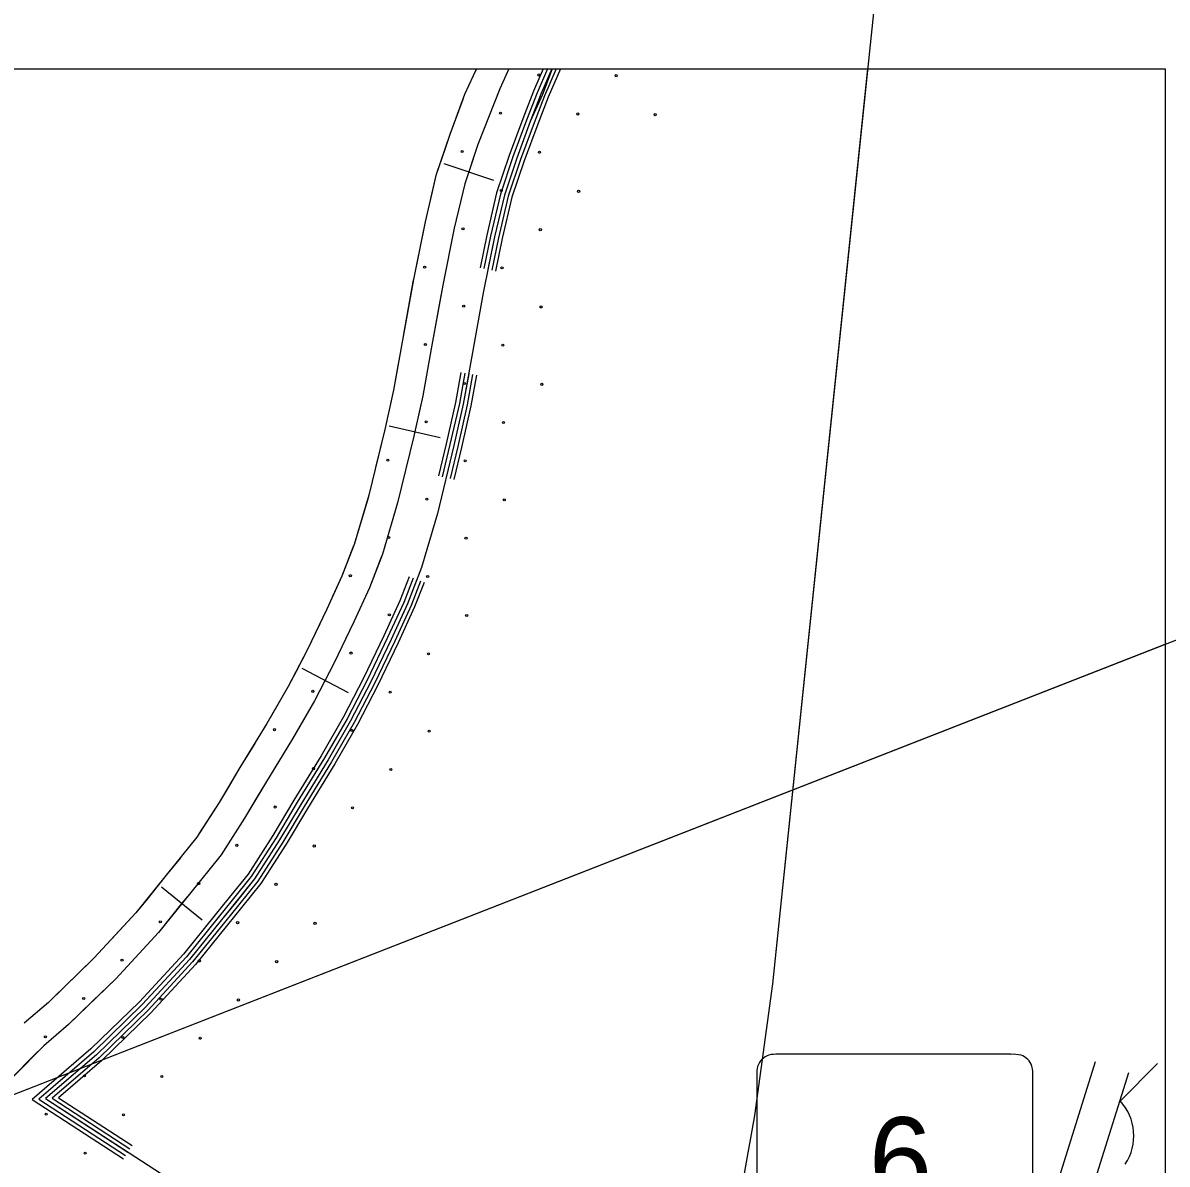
# Model space of a CAD drawing. Extents: x 1577619 to 1828281, y 483481 to 598136.
# Drawn here: x 1689939 to 1695627, y 521065 to 526740 of the extents above; entities that cross this region are included whole.
import ezdxf

# ---------------------------------------------------------------- set-up
doc = ezdxf.new("R2010")
doc.units = 0
for name, color, linetype in [('DESIGN - CENTERLINE - Proposed Text', 7, 'Continuous'), ('DESIGN - CONTOURS - Intermediate with optional Text', 7, 'Continuous'), ('DESIGN - EROSION CONTROL - Devices', 7, 'Continuous'), ('DESIGN - ROW - Slope Lines', 7, 'Continuous'), ('DESIGN - SHEET - Linework', 7, 'Continuous'), ('SURVEY - CENTERLINE - Preliminary', 7, 'Continuous'), ('SURVEY - CENTERLINE - Preliminary Text', 7, 'Continuous'), ('SURVEY - DRAINAGE - Bridge Deck with Text', 7, 'Continuous'), ('SURVEY - DRAINAGE - Natural Features', 7, 'Continuous'), ('SURVEY - VEGETATION - Features with Text', 7, 'Continuous')]:
    doc.layers.add(name, color=color, linetype=linetype)

msp = doc.modelspace()

# ---------------------------------------------------------------- linework, layer by layer
at = {"layer": 'DESIGN - CENTERLINE - Proposed Text'}
for q in [(1697294.5, 524306.5), (1695618, 523650.8)]:
    msp.add_line((1681456.9, 518112.3), q, dxfattribs=at)
at = {"layer": 'DESIGN - CONTOURS - Intermediate with optional Text'}
for p, q in [((1692031.8, 526040.7), (1692278.2, 525957.8)), ((1691760.3, 524736.3), (1692013.8, 524678.7)), ((1691325.6, 523530.6), (1691556.5, 523410.9)), ((1690628.1, 522444), (1690830.4, 522280.7))]:
    msp.add_line(p, q, dxfattribs=at)
for points in [[(1692354.3, 526510.7), (1692309.5, 526411.2), (1692200.9, 526135.9), (1692135, 525939.7), (1692083.3, 525719.5), (1692025.7, 525436.5), (1691968.8, 525118.4), (1691927.3, 524884.8), (1691881.9, 524684.9), (1691801.8, 524353.1), (1691725.7, 524097.5), (1691661.4, 523930.4), (1691583.6, 523761.7), (1691484.6, 523554.8), (1691388.1, 523368.6), (1691279.5, 523180.4), (1691144.6, 522960.1), (1691040.4, 522785), (1690924.1, 522603.4), (1690766.4, 522408.3), (1690612.2, 522217.3), (1690399.9, 521987.3), (1690166, 521759.8), (1690042.2, 521653.7)], [(1692354.3, 526510.7), (1692309.5, 526411.2), (1692200.9, 526135.9), (1692155, 525999.3)], [(1692155, 525999.3), (1692135, 525939.7), (1692083.3, 525719.5), (1692025.7, 525436.5), (1692011.2, 525355.6)], [(1692011.2, 525355.6), (1691968.8, 525118.4), (1691927.3, 524884.8), (1691887, 524707.5)], [(1691887, 524707.5), (1691881.9, 524684.9), (1691801.8, 524353.1), (1691725.7, 524097.5), (1691715.3, 524070.6)], [(1691715.3, 524070.6), (1691661.4, 523930.4), (1691583.6, 523761.7), (1691484.6, 523554.8), (1691441.1, 523470.8)], [(1691441.1, 523470.8), (1691388.1, 523368.6), (1691279.5, 523180.4), (1691144.6, 522960.1), (1691109.1, 522900.5)], [(1691109.1, 522900.5), (1691040.4, 522785), (1690924.1, 522603.4), (1690766.4, 522408.3), (1690729.3, 522362.4)], [(1690729.3, 522362.4), (1690612.2, 522217.3), (1690399.9, 521987.3), (1690284.8, 521875.3)], [(1690284.8, 521875.3), (1690166, 521759.8), (1690042.2, 521653.7)], [(1687255, 518732.8), (1688399.1, 519989.9), (1689031.6, 520639.6), (1689595.9, 521203.2), (1690042.2, 521653.7)], [(1689987.2, 521598.1), (1690042.2, 521653.7)], [(1689522.2, 521129.7), (1689595.9, 521203.2), (1689987.2, 521598.1)]]:
    msp.add_lwpolyline(points, dxfattribs=at)
at = {"layer": 'DESIGN - EROSION CONTROL - Devices'}
for centre in [(1692503.5, 526481.1), (1692888, 526477.4), (1692313.1, 526290.7), (1692697.6, 526287), (1693082.2, 526283.3), (1692122.7, 526100.3), (1692507.2, 526096.6), (1692316.8, 525906.2), (1692701.4, 525902.4), (1692126.4, 525715.8), (1692510.9, 525712), (1691936, 525525.4), (1692320.5, 525521.6), (1692130.1, 525331.2), (1692514.7, 525327.5), (1691939.7, 525140.8), (1692324.3, 525137.1), (1692133.9, 524946.7), (1692518.4, 524942.9), (1691943.5, 524756.2), (1692328, 524752.5), (1691753, 524565.8), (1692137.6, 524562.1), (1691947.2, 524371.7), (1692331.7, 524368), (1691756.8, 524181.3), (1692141.3, 524177.6), (1691566.4, 523990.9), (1691950.9, 523987.1), (1691760.5, 523796.7), (1692145.1, 523793), (1691570.1, 523606.3), (1691954.7, 523602.6), (1691379.7, 523415.9), (1691764.2, 523412.2), (1691189.3, 523225.5), (1691573.8, 523221.8), (1691958.4, 523218), (1691383.4, 523031.4), (1691768, 523027.6), (1691193, 522840.9), (1691577.6, 522837.2), (1691002.6, 522650.5), (1691387.2, 522646.8), (1690812.2, 522460.1), (1691196.7, 522456.4), (1690621.8, 522269.7), (1691006.3, 522266), (1691390.9, 522262.3), (1690431.4, 522079.3), (1690815.9, 522075.6), (1691200.5, 522071.8), (1690241, 521888.9), (1690625.5, 521885.2), (1691010.1, 521881.4), (1690050.6, 521698.5), (1690435.1, 521694.8), (1690819.7, 521691), (1690244.7, 521504.3), (1690629.3, 521500.6), (1690054.3, 521313.9), (1690438.8, 521310.2), (1690248.4, 521119.8)]:
    msp.add_circle(centre, 5.28, dxfattribs=at)
at = {"layer": 'DESIGN - ROW - Slope Lines'}
for p, q in [((1694849.3, 521611.1), (1693692.4, 521611.1)), ((1693587.2, 521509.8), (1693587.2, 520678.1)), ((1694960.1, 520679.5), (1694960.1, 521499.4))]:
    msp.add_line(p, q, dxfattribs=at)
for centre, radius, start, end in [((1693676.1, 521522.2), 89.8, 108.3712, 161.4495), ((1693683.1, 521451), 160.4, 86.6485, 102.7003), ((1694858.4, 521413), 198.2, 77.6972, 92.6427), ((1694870.6, 521521.6), 90.3, 20.2626, 70.5275), ((1693800, 521511), 212.8, 169.2361, 180.3208), ((1694706.5, 521503.7), 253.6, 359.0167, 11.1675)]:
    msp.add_arc(centre, radius, start, end, dxfattribs=at)
at = {"layer": 'DESIGN - SHEET - Linework'}
msp.add_lwpolyline([(1669171.5, 526510.7), (1695618, 526510.7), (1695618, 508119.9), (1669171.5, 508119.9)], close=True, dxfattribs=at)
at = {"layer": 'SURVEY - CENTERLINE - Preliminary'}
for points in [[(1699664.1, 538980.8), (1699319.1, 538409.9), (1698972.3, 537842.5), (1695481.3, 532468.9), (1695357.3, 532233.8), (1695216.5, 531898.8), (1695066.9, 531469.7), (1694585.2, 529330), (1694371.3, 528155.8), (1694207.2, 527174.4), (1693664.5, 521961.3), (1693575.1, 521307.5), (1693482.8, 520785.8), (1693198.2, 519751.4), (1691958.7, 516195.2)], [(1699664.1, 538980.8), (1699319.1, 538409.9), (1698972.3, 537842.5), (1695481.3, 532468.9), (1695357.3, 532233.8), (1695216.5, 531898.8), (1695066.9, 531469.7), (1694585.2, 529330), (1694371.3, 528155.8), (1694207.2, 527174.4), (1693664.5, 521961.3), (1693575.1, 521307.5), (1693482.8, 520785.8), (1693198.2, 519751.4), (1691958.7, 516195.2)], [(1694138.1, 526510.7), (1693664.5, 521961.3), (1693575.1, 521307.5), (1693482.8, 520785.8), (1693198.2, 519751.4), (1691958.7, 516195.2)], [(1694138.1, 526510.7), (1693664.5, 521961.3), (1693575.1, 521307.5), (1693482.8, 520785.8), (1693198.2, 519751.4), (1691958.7, 516195.2)]]:
    msp.add_lwpolyline(points, dxfattribs=at)
at = {"layer": 'SURVEY - CENTERLINE - Preliminary Text'}
for points in [[(1695269.4, 521574.5), (1694992.2, 520687.8), (1694894.5, 520468.7), (1694713.7, 520191.2), (1694544.4, 519986.7)], [(1695434.9, 521519.3), (1695155.6, 520626), (1695048.2, 520385), (1694854.4, 520087.6), (1694679.2, 519876)]]:
    msp.add_lwpolyline(points, dxfattribs=at)
at = {"layer": 'SURVEY - DRAINAGE - Bridge Deck with Text'}
msp.add_line((1695579.9, 521565.4), (1695393, 521378.6), dxfattribs=at)
msp.add_arc((1695207.3, 521206.3), 254.2, 326.2853, 43.0079, dxfattribs=at)
at = {"layer": 'SURVEY - DRAINAGE - Natural Features'}
for points in [[(1692569.4, 526510.7), (1692522.4, 526384.6), (1692461.3, 526249.5), (1692393.8, 526066.7), (1692332.2, 525883.5), (1692283.4, 525675.6), (1692226.9, 525398), (1692170.5, 525082.4), (1692128.1, 524844.1), (1692081.3, 524638.2), (1691999.7, 524299.8), (1691919.7, 524031.4), (1691850.2, 523850.7), (1691769, 523674.5), (1691668, 523463.4), (1691567.8, 523270.2), (1691455.6, 523075.6), (1691320, 522854.2), (1691214.7, 522677.4), (1691090.5, 522483.4), (1690925.7, 522279.6), (1690767.4, 522083.4), (1690546.7, 521844.3), (1690304.2, 521608.4), (1690050.6, 521391.1), (1692863.1, 519564.5)], [(1692568.3, 526510.7), (1692513.3, 526385.3), (1692461.3, 526249.5), (1692393.8, 526066.7), (1692332.2, 525883.5), (1692283.4, 525675.6), (1692226.9, 525398), (1692170.5, 525082.4), (1692128.1, 524844.1), (1692081.3, 524638.2), (1691999.7, 524299.8), (1691919.7, 524031.4), (1691850.2, 523850.7), (1691769, 523674.5), (1691668, 523463.4), (1691567.8, 523270.2), (1691455.6, 523075.6), (1691320, 522854.2), (1691214.7, 522677.4), (1691090.5, 522483.4), (1690925.7, 522279.6), (1690767.4, 522083.4), (1690546.7, 521844.3), (1690304.2, 521608.4), (1690050.6, 521391.1), (1692863.1, 519564.5)], [(1692524.6, 526510.7), (1692476.3, 526400.5), (1692423.9, 526263.6), (1692356.1, 526080), (1692293.7, 525894.5), (1692244.3, 525684.2), (1692211.3, 525521.8)], [(1692546.5, 526510.7), (1692494.8, 526392.9), (1692442.6, 526256.5), (1692374.9, 526073.3), (1692313, 525889), (1692263.8, 525679.9), (1692230.9, 525517.8)], [(1692568.3, 526510.7), (1692513.3, 526385.3), (1692461.3, 526249.5), (1692393.8, 526066.7), (1692332.2, 525883.5), (1692283.4, 525675.6), (1692250.5, 525513.8)], [(1692590.1, 526510.7), (1692531.8, 526377.7), (1692480.1, 526242.5), (1692412.6, 526060), (1692351.5, 525878), (1692302.9, 525671.4), (1692270.1, 525509.9)], [(1692610.9, 526510.7), (1692549.4, 526370.5), (1692497.9, 526235.8), (1692430.6, 526053.7), (1692369.8, 525872.8), (1692321.5, 525667.3), (1692288.7, 525506.1)], [(1692115.5, 525001.6), (1692088.9, 524852.1), (1692042.4, 524647.3), (1692004, 524488.1)], [(1692135.2, 524998.1), (1692108.5, 524848.1), (1692061.9, 524642.7), (1692023.4, 524483.4)], [(1692154.9, 524994.6), (1692128.1, 524844.1), (1692081.3, 524638.2), (1692042.9, 524478.7)], [(1692174.6, 524991.1), (1692147.7, 524840.2), (1692100.8, 524633.6), (1692062.3, 524474.1)], [(1692193.3, 524987.7), (1692166.3, 524836.4), (1692119.3, 524629.3), (1692080.8, 524469.6)], [(1691859.4, 523986.1), (1691813.4, 523866.2), (1691732.8, 523691.6), (1691632.1, 523481.2), (1691532.7, 523289.4), (1691421.2, 523096.1), (1691285.7, 522874.9), (1691180.6, 522698.4), (1691058, 522506.8), (1690963.7, 522390.2)], [(1691878.1, 523979), (1691831.8, 523858.5), (1691750.9, 523683.1), (1691650.1, 523472.3), (1691550.3, 523279.8), (1691438.4, 523085.9), (1691302.8, 522864.6), (1691197.7, 522687.9), (1691074.2, 522495.1), (1690979.2, 522377.6)], [(1691896.8, 523971.8), (1691850.2, 523850.7), (1691769, 523674.5), (1691668, 523463.4), (1691567.8, 523270.2), (1691455.6, 523075.6), (1691320, 522854.2), (1691214.7, 522677.4), (1691090.5, 522483.4), (1690994.8, 522365)], [(1691915.5, 523964.6), (1691868.7, 523842.9), (1691787.1, 523666), (1691685.9, 523454.5), (1691585.4, 523260.6), (1691472.8, 523065.4), (1691337.1, 522843.9), (1691231.7, 522666.8), (1691106.7, 522471.7), (1691010.3, 522352.4)], [(1691933.2, 523957.8), (1691886.2, 523835.5), (1691804.3, 523658), (1691702.9, 523446), (1691602, 523251.5), (1691489.1, 523055.7), (1691353.3, 522834.1), (1691247.9, 522656.9), (1691122.2, 522460.6), (1691025.1, 522340.5)], [(1690963.7, 522390.2), (1690894.6, 522304.7), (1690737.1, 522109.5), (1690518, 521872.3), (1690277.2, 521638), (1689984, 521386.7), (1690438.5, 521091.5)], [(1690979.2, 522377.6), (1690910.2, 522292.1), (1690752.2, 522096.4), (1690532.4, 521858.3), (1690290.7, 521623.2), (1690017.3, 521388.9), (1690449.3, 521108.3)], [(1690994.8, 522365), (1690925.7, 522279.6), (1690767.4, 522083.4), (1690546.7, 521844.3), (1690304.2, 521608.4), (1690050.6, 521391.1), (1690460.2, 521125.1)], [(1691010.3, 522352.4), (1690941.3, 522267), (1690782.5, 522070.3), (1690561, 521830.4), (1690317.7, 521593.7), (1690083.9, 521393.3), (1690471.1, 521141.9)], [(1691025.1, 522340.5), (1690956.1, 522255), (1690796.9, 522057.9), (1690574.6, 521817.1), (1690330.5, 521579.6), (1690115.6, 521395.4), (1690481.5, 521157.8)]]:
    msp.add_lwpolyline(points, dxfattribs=at)
at = {"layer": 'SURVEY - VEGETATION - Features with Text'}
for points in [[(1692193.6, 526510.7), (1692176.8, 526477.4), (1692134.4, 526383.6), (1692060.7, 526184.2), (1691992.2, 525980.4), (1691938.4, 525751.2), (1691880, 525464.3), (1691822.8, 525144.4), (1691781.9, 524914.2), (1691737.5, 524718.7), (1691658.6, 524391.7), (1691585.2, 524145.4), (1691524.8, 523988.1), (1691449.4, 523824.7), (1691351.9, 523620.9), (1691258, 523439.8), (1691152, 523256.1), (1691017.7, 523036.8), (1690914.2, 522863), (1690803.6, 522690.3), (1690651, 522501.4), (1690499.9, 522314.3), (1690293.7, 522090.9), (1690065.9, 521869.3), (1689945.7, 521766.3)], [(1692192.7, 526510.7), (1692186.3, 526496.3)], [(1692125.4, 526359.3), (1692060.7, 526184.2), (1692036.1, 526110.9)], [(1692036.1, 526110.9), (1691992.2, 525980.4), (1691963.3, 525857.4)], [(1691930.2, 525711.1), (1691880, 525464.3), (1691877.9, 525452.3)], [(1691877.9, 525452.4), (1691831.4, 525192.5)], [(1691805.1, 525044.8), (1691781.9, 524914.2), (1691752.8, 524786.1)], [(1691752.8, 524786.1), (1691737.5, 524718.7), (1691691.8, 524529.3)], [(1691656.2, 524383.5), (1691585.2, 524145.4), (1691579.6, 524130.9)], [(1691579.6, 524130.9), (1691524.8, 523988.1), (1691478.3, 523887.3)], [(1691414.4, 523751.6), (1691351.9, 523620.9), (1691297, 523515.1)], [(1691297, 523515.2), (1691258, 523439.8), (1691168.5, 523284.6)], [(1691090.9, 523156.3), (1691017.7, 523036.8), (1690954.3, 522930.3)], [(1690954.3, 522930.4), (1690914.2, 522863), (1690814.1, 522706.7)], [(1690721.6, 522588.8), (1690651, 522501.4), (1690555.7, 522383.4)], [(1690555.7, 522383.4), (1690499.9, 522314.3), (1690381.1, 522185.6)], [(1690278.5, 522076.1), (1690089.3, 521892)], [(1690089.3, 521892), (1690065.9, 521869.3), (1689945.7, 521766.3)]]:
    msp.add_lwpolyline(points, dxfattribs=at)

# ---------------------------------------------------------------- texts
at = {"layer": 'DESIGN - ROW - Slope Lines'}
msp.add_text('6', height=422.4, rotation=0.0013, dxfattribs=at).set_placement((1694144.4, 520875.8))

doc.saveas('drawing.dxf')
